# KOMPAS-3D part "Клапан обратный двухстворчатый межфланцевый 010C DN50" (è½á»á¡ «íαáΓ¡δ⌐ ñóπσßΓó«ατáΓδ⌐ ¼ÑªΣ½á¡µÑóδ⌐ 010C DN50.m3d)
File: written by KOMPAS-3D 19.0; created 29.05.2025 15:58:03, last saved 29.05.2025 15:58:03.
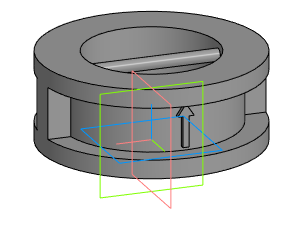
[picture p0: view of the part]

Document properties: Полное имя файла: E:\Dendor Работа Сачек\3D для проекитирвщиков\5.2 Тип 010C, 010C.Y Клапан обратный двухстворчатый межфланцевый\stp_Клапан обратный двухстворчатый межфланцевый 010C\Клапан обратный двухстворчатый межфланцевый 010C DN50.m3d

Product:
- Part/product: Клапан обратный двухстворчатый межфланцевый 010C DN50

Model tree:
1. Операция без истории:1  (labels: Клапан обратный двухстворчатый межфланцевый 010C DN50)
